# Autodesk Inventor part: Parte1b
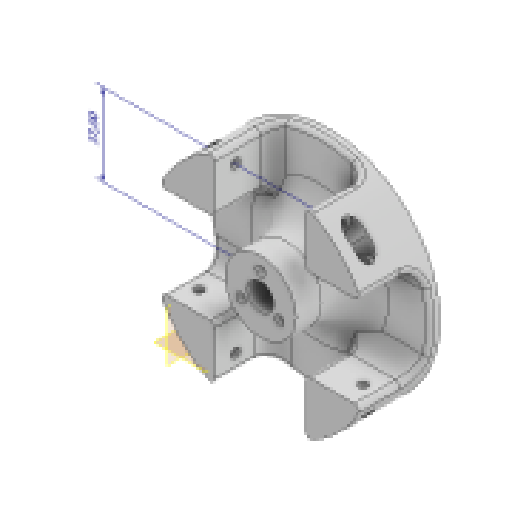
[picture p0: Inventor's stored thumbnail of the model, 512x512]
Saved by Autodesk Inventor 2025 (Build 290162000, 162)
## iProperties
Created: 2025-05
Part Number: Parte1b
Material: Generico
Document SubType Name: Modeling
Designer: R5800u
Density: 1 g/cm^3
Appearance: Default
Author: R5800u
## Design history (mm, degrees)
node "Annotazioni"
  node "Quota lineare 1" dims "d0" = 100, "d1" = 45 deg, "d3" = 25, "d8" = 6, "d9" = 6, "d10" = 3, "d11" = 3, "d22" = 6, "d23" = 6, "d45" = 37 (derived)
sketch "Schizzo1" dims "d0" = 100
  geometry: L1 (0, 0)-(35.355, 35.355); L2 (0, 0)-(50, 0); L3 (20.572, 20.572)-(20.572, 45.572); L4 (20.572, 20.572)-(45.572, 20.572); L5 (0, 0)-(0, 44.829) reference; L6 (-20.572, 20.572)-(-20.572, 45.572); L7 (0, 0)-(-35.355, 35.355); L8 (-20.572, 20.572)-(-45.572, 20.572); L9 (0, 0)-(56.569, 0); L10 (26.572, 42.355)-(26.572, 26.572); L11 (26.572, 26.572)-(42.355, 26.572); L12 (-26.572, 42.355)-(-26.572, 26.572); L13 (-26.572, 26.572)-(-42.355, 26.572); L14 (-20.572, 24.815)-(0, 4.243); L15 (0, 4.243)-(20.572, 24.815); L16 (24.815, 20.572)-(0, -4.243); L17 (0, -4.243)-(-24.815, 20.572); L18 (20.572, -20.572)-(20.572, -45.572); L19 (0, -4.243)-(20.572, -24.815); L20 (26.572, -42.355)-(26.572, -26.572); L21 (24.815, -20.572)-(0, 4.243); L22 (0, 0)-(35.355, -35.355); L23 (26.572, -26.572)-(42.355, -26.572); L24 (20.572, -20.572)-(45.572, -20.572); L25 (0, 0)-(0, -44.829); L26 (-20.572, -24.815)-(0, -4.243); L27 (0, 4.243)-(-24.815, -20.572); L28 (0, 0)-(-35.355, -35.355); L29 (-20.572, -20.572)-(-20.572, -45.572); L30 (-26.572, -42.355)-(-26.572, -26.572); L31 (-26.572, -26.572)-(-42.355, -26.572); L32 (-20.572, -20.572)-(-45.572, -20.572); 3 further points
  constraints: 64 end point, 25 symmetric about line, 13 point on line, 3 vertical, 2 coincident, 2 horizontal, 1 equal length, 9 other
  dimensions: "d1" = 45 deg angle of L2 L1; "d3" = 25 distance of L3.start L4.end; "d8" = 6 distance between parallel lines of L3 L10; "d9" = 6 distance between parallel lines of L6 L12; "d10" = 3 distance between parallel lines of L7 L14; "d11" = 3 distance between parallel lines of L1 L16; "d22" = 6 distance between parallel lines of L4 L11; "d23" = 6 distance between parallel lines of L8 L13
extrude "Estrusione1" new body sketch "Schizzo1" stored distance "d4" = 75; taper "d5" = 0 deg
node "Piano di lavoro1"
sketch "Schizzo3" dims "d24" = 100
  geometry: L1 (0, 0)-(35.355, 35.355); L2 (0, 0)-(50, 0); L3 (20.572, 20.572)-(20.572, 45.572); L4 (20.572, 20.572)-(45.572, 20.572); L5 (0, 0)-(0, 44.829); L6 (-20.572, 20.572)-(-20.572, 45.572); L7 (0, 0)-(-35.355, 35.355); L8 (-20.572, 20.572)-(-45.572, 20.572); L9 (0, 0)-(56.569, 0); L10 (26.572, 42.355)-(26.572, 26.572); L11 (26.572, 26.572)-(42.355, 26.572); L12 (-26.572, 42.355)-(-26.572, 26.572); L13 (-26.572, 26.572)-(-42.355, 26.572); L14 (-20.572, 24.815)-(0, 4.243); L15 (0, 4.243)-(20.572, 24.815); L16 (24.815, 20.572)-(0, -4.243); L17 (0, -4.243)-(-24.815, 20.572); L18 (20.572, -20.572)-(20.572, -45.572); L19 (0, -4.243)-(20.572, -24.815); L20 (26.572, -42.355)-(26.572, -26.572); L21 (24.815, -20.572)-(0, 4.243); L22 (0, 0)-(35.355, -35.355); L23 (26.572, -26.572)-(42.355, -26.572); L24 (20.572, -20.572)-(45.572, -20.572); L25 (0, 0)-(0, -44.829); L26 (-20.572, -24.815)-(0, -4.243); L27 (0, 4.243)-(-24.815, -20.572); L28 (0, 0)-(-35.355, -35.355); L29 (-20.572, -20.572)-(-20.572, -45.572); L30 (-26.572, -42.355)-(-26.572, -26.572); L31 (-26.572, -26.572)-(-42.355, -26.572); L32 (-20.572, -20.572)-(-45.572, -20.572); 16 further points
  constraints: 64 end point, 25 symmetric about line, 13 point on line, 2 coincident, 2 horizontal, 2 parallel, 2 vertical, 1 equal length, 9 other
  dimensions: "d25" = 45 deg angle of L2 L1; "d26" = 25 distance of L3.start L4.end; "d27" = 6 distance between parallel lines of L3 L10; "d28" = 6 distance between parallel lines of L6 L12; "d29" = 3 distance between parallel lines of L7 L14; "d30" = 3 distance between parallel lines of L1 L16; "d31" = 6 distance between parallel lines of L4 L11; "d32" = 6 distance between parallel lines of L8 L13; "d41" = 3 distance between parallel lines of L1 L15; "d42" = 3 distance between parallel lines of L7 L17; "d63" = 25 distance of L18.start L24.end (derived); "d64" = 25 distance of L18.start L18.end (derived); "d65" = 41.14378 distance between parallel lines of L32 L8 (derived); "d66" = 41.14378 distance between parallel lines of L24 L4 (derived); "d67" = 41.14378 distance between parallel lines of L3 L6 (derived); "d68" = 41.14378 distance between parallel lines of L18 L29 (derived)
extrude "Estrusione4" cut sketch "Schizzo3" extent not by distance; stored distance "d33" = 30; taper "d34" = 0 deg
sketch "Schizzo4"
  geometry: L1 (45.572, 37.5)-(45.572, 3) reference; L2 (45.572, 20.25)-(0, 20.25); L3 (0, 3)-(0, 37.5) reference; C1 r 2 at (37, 20.25); 2 further points
  constraints: 2 end point, 2 midpoint, 1 centre point, 1 coincident, 1 point on line
  dimensions: "d36" = 37 horizontal distance of point (0, 0) point (37, 20.25); "d37" = 4 diameter of C1
extrude "Estrusione5" cut sketch "Schizzo4" extent not by distance; stored distance "d38" = 0; taper "d39" = 0 deg
pattern_circular "Serie circolare1" dims angle "d47" = 360 deg
sketch "Schizzo5"
  geometry: C1 r 50 at (0, 0) reference; 1 further point
extrude "Estrusione6" cut sketch "Schizzo5" distance "d53" = 36; taper "d54" = 0 deg
sketch "Schizzo6"
  geometry: L1 (45.572, -20.572)-(20.572, -20.572) reference; L2 (20.572, 20.572)-(45.572, 20.572) reference; L3 (20.572, 45.572)-(20.572, 20.572) reference; L4 (-20.572, 20.572)-(-20.572, 45.572) reference; L5 (-45.572, 20.572)-(-20.572, 20.572) reference; L6 (-20.572, -20.572)-(-45.572, -20.572) reference; L7 (-20.572, -45.572)-(-20.572, -20.572) reference; L8 (20.572, -20.572)-(20.572, -45.572) reference; L9 (-20.572, 24.815)-(-24.815, 20.572); L10 (-24.815, 20.572)-(-20.572, 24.815); L11 (-24.815, -20.572)-(-20.572, -24.815); L12 (20.572, 24.815)-(24.815, 20.572); L13 (24.815, -20.572)-(20.572, -24.815); C1 r 16 at (0, 0); A1 r 50 centre (0, 0) between (45.572, 20.572) and (20.572, 45.572) reference; A2 r 50 centre (0, 0) between (-20.572, 45.572) and (-45.572, 20.572) reference; A3 r 50 centre (0, 0) between (-45.572, -20.572) and (-20.572, -45.572) reference; A4 r 50 centre (0, 0) between (20.572, -45.572) and (45.572, -20.572) reference; A5 r 35 centre (0, 53.131) between (-20.572, 24.815) and (20.572, 24.815); A6 r 35 centre (-53.131, 0) between (-24.815, -20.572) and (-24.815, 20.572); A7 r 35 centre (0, -53.131) between (20.572, -24.815) and (-20.572, -24.815); A8 r 35 centre (53.131, 0) between (24.815, 20.572) and (24.815, -20.572); 1 further point
  constraints: 10 end point, 8 point on circle, 5 centre point, 1 coincident, 1 parallel, 1 perpendicular, 17 other
  dimensions: "d55" = 32 diameter of C1; "d109" = 35 radius of A5; "d112" = 360 deg dimension on point (0, 0) A5.centre (derived)
extrude "Estrusione7" join sketch "Schizzo6" stored distance "d56" = 36; taper "d57" = 0 deg
sketch "Schizzo7"
  geometry: C1 r 2.5 at (0, 0); 1 further point
  constraints: 1 centre point, 1 coincident
  dimensions: "d69" = 5 diameter of C1
extrude "Estrusione8" cut sketch "Schizzo7" extent not by distance; stored distance "d70" = 10; taper "d71" = 0 deg
sketch "Schizzo8"
  geometry: L1 (20.572, 20.572)-(45.572, 20.572) reference; L2 (20.572, 45.572)-(20.572, 20.572) reference; L3 (-20.572, 20.572)-(-20.572, 45.572) reference; L4 (-45.572, 20.572)-(-20.572, 20.572) reference; L5 (-20.572, -20.572)-(-45.572, -20.572) reference; L6 (-20.572, -45.572)-(-20.572, -20.572) reference; L7 (20.572, -20.572)-(20.572, -45.572) reference; L8 (45.572, -20.572)-(20.572, -20.572) reference; A1 r 50 centre (0, 0) between (45.572, 20.572) and (20.572, 45.572) reference; A2 r 50 centre (0, 0) between (20.572, -45.572) and (45.572, -20.572) reference; A3 r 50 centre (0, 0) between (-45.572, -20.572) and (-20.572, -45.572) reference; A4 r 50 centre (0, 0) between (-20.572, 45.572) and (-45.572, 20.572) reference; A5 r 35 centre (0, 53.131) between (-20.572, 24.815) and (20.572, 24.815); A6 r 35 centre (-53.131, 0) between (-24.815, -20.572) and (-24.815, 20.572); A7 r 35 centre (0, -53.131) between (20.572, -24.815) and (-20.572, -24.815); A8 r 35 centre (53.131, 0) between (24.815, 20.572) and (24.815, -20.572); 9 further points
  constraints: 8 point on circle, 4 centre point, 17 other
  dimensions: "d104" = 35 radius of A5; "d107" = 360 deg dimension on point (0, 0) A5.centre (derived)
extrude "Estrusione9" cut sketch "Schizzo8" distance "d72" = 8; taper "d73" = 0 deg
node "Piano di lavoro3"
sketch "Schizzo10"
  geometry: C1 r 2 at (-17.25, 8.572) reference; C2 r 4 at (-17.25, 8.572); 1 further point
  constraints: 1 centre point, 1 coincident
  dimensions: "d86" = 8 diameter of C2
extrude "Estrusione11" cut sketch "Schizzo10" distance "d87" = 13; taper "d88" = 0 deg
node "Piano di lavoro4"
sketch "Schizzo11"
  geometry: C1 r 2 at (8.572, -17.25) reference; C2 r 4 at (8.572, -17.25); 1 further point
  constraints: 1 centre point, 1 coincident
  dimensions: "d90" = 8 diameter of C2
extrude "Estrusione12" cut sketch "Schizzo11" distance "d91" = 13; taper "d92" = 0 deg
pattern_circular "Serie circolare4" dims "d94" = 360 deg
fillet "Raccordo21" dims "d124" = 6
fillet "Raccordo22" dims "d125" = 8
fillet "Raccordo23" dims "d126" = 2
fillet "Raccordo24" dims "d127" = 15
sketch "Schizzo12"
  geometry: C1 r 2.5 at (0, 0) reference; C2 r 6 at (0, 0); 1 further point
  constraints: 1 centre point, 1 coincident
  dimensions: "d128" = 12 diameter of C2
extrude "Estrusione13" cut sketch "Schizzo12" distance "d129" = 13; taper "d130" = 0 deg
sketch "Schizzo13"
  geometry: C1 r 1.6 at (0, 10) reference; C2 r 1.55 at (-8.66, -5) reference; C3 r 1.6 at (8.66, -5) reference; 1 further point
hole "Foro1" sketch "Schizzo13" at (-8.66, -5), (0, 10), (8.66, -5) diameter "d131" = 3.2; stored, may be unused: countersink angle "d135" = 90 deg, drill point angle "d137" = 118 deg; dims "d132" = 6, "d133" = 9.4, "d134" = 2, "d136" = 11.5
fillet "Raccordo25" dims "d138" = 2
node "Solido1"
node "Linea chiusa proiettata1"
node "Schizzo - Serie circolare1" dims "d107" = 360 deg (derived)
node "Linea chiusa proiettata2"
node "Schizzo - Serie circolare2" dims "d112" = 360 deg (derived)
node "Riferimento1"
node "Riferimento2"
node "Riferimento3"
other parameters: "d12" = 3, "d18" = 2, "d19" = 2, "d43" = -3.54436 (derived), "d44" = -20.19224 (derived)
